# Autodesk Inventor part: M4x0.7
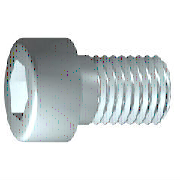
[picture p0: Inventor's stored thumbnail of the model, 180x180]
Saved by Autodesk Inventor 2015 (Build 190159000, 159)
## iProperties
IsCustomPart: 1
Created: 2015-10
Part Number: M4x0.7
Material: 강, 연강
Description: 6각머리 태핑 나사
Document SubType Name: Modeling
Standard: KS B 1003
Designer: mdu
Standards Organization: KS
Language: ko-KR
Size Designation: M 4 x 16
Categories: <MemberInstance><Categories><Category DisplayName="조임쇠" InternalName="e4da775c-781d-43d5-af7c-5136215cf5a6" Mnemonic="FSTN"><Category DisplayName="볼트" InternalN
Density: 7.85 g/cm^3
Appearance: 강철
Mass: 2.62639 g
Surface Area: 3.81118 cm^2
Volume: 0.334572 cm^3
Author: mdu
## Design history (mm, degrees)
sketch "스케치1"
  geometry: L1 (-1, 0)-(16, 0); L2 (16, 0)-(16, 2); L3 (16, 2)-(1.75, 2); L4 (1.75, 2)-(1.32, 2); L5 (1.32, 2)-(0, 2); L6 (0, 2)-(0, 3.5); L7 (0, 3.5)-(-4, 3.5); L8 (-4, 3.5)-(-4, 1.732); L9 (-4, 1.732)-(-2, 1.732); L10 (-2, 1.732)-(-1, 0); L11 (-8, 0)-(20, 0) reference; L12 (0, -0.7)-(0, 4.2) reference; L13 (1.75, 2)-(0, 2)
  constraints: 22 end point, 6 parallel, 2 collinear, 2 perpendicular, 1 horizontal, 1 point on line
  dimensions: "d1" = 14.25 distance from line of L3.end L2 (= GEL); "d2" = 0.42952 distance of L4.end L3.end (computed from GAL); "d3" = 4 distance between parallel lines of L8 L6 (= KOH); "d4" = 2 distance of L8.end L9.end (= INTI); "d5" = 60 deg angle of L10 L1; "d6" = 4 diameter of L3 L1 (= GD); "d7" = 4 diameter of L5 L1 (= BDM); "d8" = 3.4641 diameter of L9 L1 (= 1.1547 x SW); "d9" = 7 diameter of L7 L1 (= KOD); "d26" = 16 distance between parallel lines of L12 L2 (= NLG)
revolve "본체" sketch "스케치1" stored, may be unused: angle "d10" = 90 deg
sketch "스케치2"
  geometry: L1 (0, -4.9)-(0, 4.9) reference; L2 (-4.9, 0)-(4.9, 0) reference; L3 (1.732, 0)-(0.866, -1.5); L4 (0.866, -1.5)-(-0.866, -1.5); L5 (-0.866, -1.5)-(-1.732, 0); L6 (-1.732, 0)-(-0.866, 1.5); L7 (-0.866, 1.5)-(0.866, 1.5); L8 (0.866, 1.5)-(1.732, 0); 2 further points
  constraints: 12 end point, 1 coincident, 1 horizontal alignment, 1 point on line, 12 other
extrude "슬롯" join sketch "스케치2" stored distance "d11" = 10; taper "d12" = 0 deg
workplane "Work Plane1"
fillet "Fillet2" dims "d30" = 0.1 (= R)
body "Solid1"
fillet "모깎기1" dims "d17" = 0.4 (= RR)
feature "스레드" dims "d13" = 14.25 (= GEL), "d14" = 0
chamfer "모따기1" distance "d15" = 0.42941 (= -0.5 x SPD + 0.5 x GD); stored, may be unused: second distance "d16" = 0.42941 (= GUL), angle "d27" = 45 deg
other parameters: "GD" = 4 (= NND) [user parameter; used in 2 equation terms], "NLG" = 16 [user parameter; used in 1 equation term], "GEL" = 14.25 [user parameter; used in 2 equation terms], "KOD" = 7 [user parameter; used in 1 equation term], "KOH" = 4 [user parameter; used in 1 equation term], "INTI" = 2 [user parameter; used in 1 equation term], "GAL" = 0.42941 (= 0.61345 x PTC) [user parameter; used in 1 equation term], "GUL" = 0.42941 (= 0.61345 x PTC) [user parameter; used in 1 equation term], "BDM" = 4 (= NND) [user parameter; used in 1 equation term], "SW" = 3 [user parameter; used in 2 equation terms], "RR" = 0.4 [user parameter; used in 1 equation term], "SPD" = 3.14117 (= NND - 1.2269 x PTC) [user parameter; used in 1 equation term], "d19" = 0, "d28" = 0, "d29" = 0, "R" = 0.1 [user parameter; used in 1 equation term], "PHH" = 0.2 [user parameter], "GD1" = 3.14117 (= THREADDIA - 1.2269 x PTC) [user parameter], "THREADDIA" = 4 [user parameter; used in 1 equation term], "FAWI" = 45 deg [user parameter], "TPU" = 14.28571 (computed from PTC) [user parameter], "PTC" = 0.7 [user parameter; used in 5 equation terms], "NND" = 4 [user parameter; used in 3 equation terms], "TOA" = 30 deg [user parameter], "E0" = 3.465 (= 1.155 x SW) [user parameter]
